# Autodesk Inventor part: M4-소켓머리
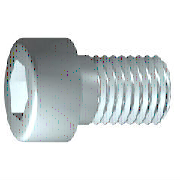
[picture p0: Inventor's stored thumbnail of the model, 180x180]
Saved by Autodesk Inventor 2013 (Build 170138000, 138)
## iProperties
IsCustomPart: 0
Company: 한국ATC센터
Created: 2014-08
Part Number: M4-소켓머리
Material: 강, 연강
Description: 6각머리 태핑 나사
Document SubType Name: Modeling
Standard: KS B 1003
Designer: KYOUNG IL JANG
Standards Organization: KS
Language: ko-KR
Size Designation: M 4 x 12
Categories: <MemberInstance><Categories><Category DisplayName="조임쇠" InternalName="e4da775c-781d-43d5-af7c-5136215cf5a6" Mnemonic="FSTN"><Category DisplayName="볼트" InternalN
Density: 7.86 g/cm^3
Checked By: KYOUNG IL JANG
Mass: 2.23465 g
Surface Area: 3.30853 cm^2
Volume: 0.284306 cm^3
Author: KYOUNG IL JANG
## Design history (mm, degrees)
sketch "스케치1"
  geometry: L1 (-1, 0)-(12, 0); L2 (12, 0)-(12, 2); L3 (12, 2)-(1.75, 2); L4 (1.75, 2)-(1.32, 2); L5 (1.32, 2)-(0, 2); L6 (0, 2)-(0, 3.5); L7 (0, 3.5)-(-4, 3.5); L8 (-4, 3.5)-(-4, 1.732); L9 (-4, 1.732)-(-2, 1.732); L10 (-2, 1.732)-(-1, 0); L11 (-7.2, 0)-(15.2, 0) reference; L12 (0, -0.7)-(0, 4.2) reference; L13 (1.75, 2)-(0, 2)
  constraints: 22 end point, 6 parallel, 2 collinear, 2 perpendicular, 1 horizontal, 1 point on line
  dimensions: "d1" = 10.25 distance from line of L3.end L2 (= GEL); "d2" = 0.42952 distance of L4.end L3.end (computed from GAL); "d3" = 4 distance between parallel lines of L8 L6 (= KOH); "d4" = 2 distance of L8.end L9.end (= INTI); "d5" = 60 deg angle of L10 L1; "d6" = 4 diameter of L3 L1 (= GD); "d7" = 4 diameter of L5 L1 (= BDM); "d8" = 3.4641 diameter of L9 L1 (= 1.1547 x SW); "d9" = 7 diameter of L7 L1 (= KOD); "d26" = 12 distance between parallel lines of L12 L2 (= NLG)
revolve "본체" sketch "스케치1" stored, may be unused: angle "d10" = 90 deg
sketch "스케치2"
  geometry: L1 (0, -4.9)-(0, 4.9) reference; L2 (-4.9, 0)-(4.9, 0) reference; L3 (1.732, 0)-(0.866, -1.5); L4 (0.866, -1.5)-(-0.866, -1.5); L5 (-0.866, -1.5)-(-1.732, 0); L6 (-1.732, 0)-(-0.866, 1.5); L7 (-0.866, 1.5)-(0.866, 1.5); L8 (0.866, 1.5)-(1.732, 0); 2 further points
  constraints: 12 end point, 1 coincident, 1 horizontal alignment, 1 point on line, 12 other
extrude "슬롯" join sketch "스케치2" stored distance "d11" = 10; taper "d12" = 0 deg
workplane "Work Plane1"
fillet "Fillet2" dims "d30" = 0.1 (= R)
body "Solid1"
fillet "모깎기1" dims "d17" = 0.4 (= RR)
feature "스레드" dims "d13" = 10.25 (= GEL), "d14" = 0
chamfer "모따기1" distance "d15" = 0.42941 (= -0.5 x SPD + 0.5 x GD); stored, may be unused: second distance "d16" = 0.42941 (= GUL), angle "d27" = 45 deg
other parameters: "GD" = 4 (= NND) [user parameter; used in 2 equation terms], "NLG" = 12 [user parameter; used in 1 equation term], "GEL" = 10.25 [user parameter; used in 2 equation terms], "KOD" = 7 [user parameter; used in 1 equation term], "KOH" = 4 [user parameter; used in 1 equation term], "INTI" = 2 [user parameter; used in 1 equation term], "GAL" = 0.42941 (= 0.61345 x PTC) [user parameter; used in 1 equation term], "GUL" = 0.42941 (= 0.61345 x PTC) [user parameter; used in 1 equation term], "BDM" = 4 (= NND) [user parameter; used in 1 equation term], "SW" = 3 [user parameter; used in 2 equation terms], "RR" = 0.4 [user parameter; used in 1 equation term], "SPD" = 3.14117 (= NND - 1.2269 x PTC) [user parameter; used in 1 equation term], "d19" = 0, "d28" = 0, "d29" = 0, "R" = 0.1 [user parameter; used in 1 equation term], "PHH" = 0.2 [user parameter], "GD1" = 3.14117 (= THREADDIA - 1.2269 x PTC) [user parameter], "THREADDIA" = 4 [user parameter; used in 1 equation term], "FAWI" = 45 deg [user parameter], "TPU" = 14.28571 (computed from PTC) [user parameter], "PTC" = 0.7 [user parameter; used in 5 equation terms], "NND" = 4 [user parameter; used in 3 equation terms], "TOA" = 30 deg [user parameter], "E0" = 3.465 (= 1.155 x SW) [user parameter]
